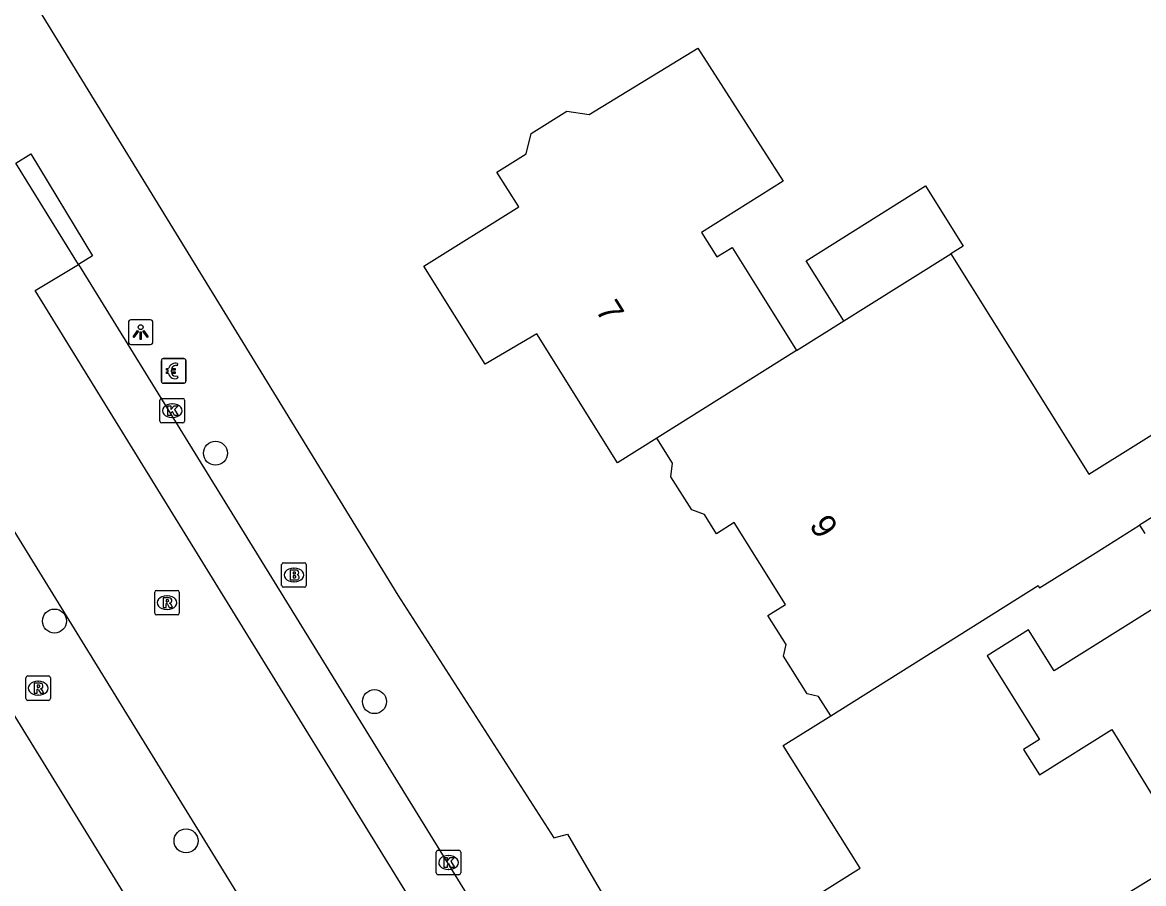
# Model space of a CAD drawing. Extents: x 161354 to 161876, y 382161 to 382804.
# Drawn here: x 161550.65 to 161596.32, y 382499.48 to 382534.56 of the extents above; entities that cross this region are included whole.
import ezdxf

# ---------------------------------------------------------------- set-up
doc = ezdxf.new("R2010")
doc.units = 0
for name, color, linetype in [('IMGEO_Betaalautomaat', 7, 'Continuous'), ('IMGEO_Boom', 7, 'Continuous'), ('IMGEO_Brandkraan', 7, 'Continuous'), ('IMGEO_Kolk', 7, 'Continuous'), ('IMGEO_Lichtpunt', 7, 'Continuous'), ('IMGEO_Pand', 7, 'Continuous'), ('IMGEO_Pand_nummerreeks', 7, 'Continuous'), ('IMGEO_Rijbaan_lokaal_gesloten', 7, 'Continuous'), ('IMGEO_Rioolput', 7, 'Continuous'), ('IMGEO_Voetpad_open', 7, 'Continuous')]:
    doc.layers.add(name, color=color, linetype=linetype)

msp = doc.modelspace()

# ---------------------------------------------------------------- linework, layer by layer
at = {"layer": 'IMGEO_Betaalautomaat'}
for p, q in [((161556.312, 382519.939), (161556.312, 382520.78)), ((161556.312, 382520.78), (161556.312, 382519.939)), ((161556.387, 382520.863), (161557.228, 382520.863)), ((161557.228, 382520.863), (161556.387, 382520.863)), ((161556.974, 382520.668), (161556.957, 382520.568)), ((161557.311, 382520.789), (161557.311, 382519.948)), ((161557.311, 382519.948), (161557.311, 382520.789)), ((161556.595, 382520.327), (161556.595, 382520.395)), ((161556.716, 382520.395), (161556.716, 382520.327)), ((161556.961, 382520.162), (161556.983, 382520.075)), ((161557.237, 382519.864), (161556.396, 382519.864)), ((161556.396, 382519.864), (161557.237, 382519.864))]:
    msp.add_line(p, q, dxfattribs=at)
for points in [[(161556.595, 382520.395), (161556.526, 382520.395), (161556.526, 382520.464), (161556.605, 382520.464)], [(161556.6, 382520.258), (161556.526, 382520.258), (161556.526, 382520.327), (161556.595, 382520.327)], [(161556.727, 382520.464), (161556.874, 382520.464), (161556.874, 382520.395), (161556.716, 382520.395)], [(161556.716, 382520.327), (161556.874, 382520.327), (161556.874, 382520.258), (161556.73, 382520.258)]]:
    msp.add_lwpolyline(points, dxfattribs=at)
for centre, radius, start, end in [((161556.39, 382520.786), 0.0779, 92.4484, 184.2845), ((161556.39, 382520.786), 0.0779, 92.4484, 184.2845), ((161556.888, 382520.388), 0.293, 73.014, 165.0139), ((161556.894, 382520.401), 0.179, 69.3236, 159.5683), ((161557.234, 382520.786), 0.0779, 2.4484, 94.2845), ((161557.234, 382520.786), 0.0779, 2.4484, 94.2845), ((161556.861, 382520.313), 0.267, 191.8096, 297.0389), ((161556.894, 382520.328), 0.179, 202.7625, 291.8693), ((161556.39, 382519.942), 0.0779, 182.4484, 274.2845), ((161556.39, 382519.942), 0.0779, 182.4484, 274.2845), ((161557.234, 382519.942), 0.0779, 272.4484, 4.2845), ((161557.234, 382519.942), 0.0779, 272.4484, 4.2845)]:
    msp.add_arc(centre, radius, start, end, dxfattribs=at)
at = {"layer": 'IMGEO_Boom'}
for centre in [(161558.515, 382517.011), (161551.957, 382510.176), (161564.991, 382506.892), (161557.316, 382501.221)]:
    msp.add_circle(centre, 0.489, dxfattribs=at)
at = {"layer": 'IMGEO_Brandkraan'}
for p, q in [((161561.212, 382511.624), (161561.212, 382512.476)), ((161561.287, 382512.55), (161562.139, 382512.55)), ((161561.7, 382512.33), (161561.725, 382512.33)), ((161562.213, 382512.476), (161562.213, 382511.624)), ((161562.139, 382511.55), (161561.287, 382511.55)), ((161561.723, 382511.77), (161561.698, 382511.77))]:
    msp.add_line(p, q, dxfattribs=at)
for points in [[(161561.212, 382511.624), (161561.212, 382512.476)], [(161561.287, 382512.55), (161562.139, 382512.55)], [(161562.213, 382512.476), (161562.213, 382511.624)], [(161561.56, 382512.25), (161561.56, 382511.85), (161561.773, 382511.85)], [(161561.791, 382512.25), (161561.56, 382512.25)], [(161561.739, 382512.169), (161561.685, 382512.169), (161561.685, 382512.093)], [(161561.685, 382512.093), (161561.738, 382512.093)], [(161561.747, 382512.017), (161561.685, 382512.017), (161561.685, 382511.936)], [(161561.685, 382511.936), (161561.747, 382511.936)], [(161562.139, 382511.55), (161561.287, 382511.55)]]:
    msp.add_lwpolyline(points, dxfattribs=at)
for centre, radius, start, end in [((161561.289, 382512.474), 0.0765, 91.552, 178.448), ((161561.289, 382512.474), 0.0765, 91.552, 178.448), ((161562.137, 382512.474), 0.0765, 1.552, 88.448), ((161562.137, 382512.474), 0.0765, 1.552, 88.448), ((161561.74, 382512.131), 0.0379, 267.8285, 90.9355), ((161561.748, 382511.976), 0.0404, 269.8759, 90.5077), ((161561.779, 382512.101), 0.251, 268.6676, 293.5347), ((161561.795, 382512.105), 0.145, 59.4692, 91.5367), ((161561.82, 382512.152), 0.0922, 285.5137, 58.1501), ((161561.825, 382511.96), 0.105, 301.3115, 78.989), ((161561.289, 382511.626), 0.0765, 181.552, 268.448), ((161561.289, 382511.626), 0.0765, 181.552, 268.448), ((161562.137, 382511.626), 0.0765, 271.552, 358.448), ((161562.137, 382511.626), 0.0765, 271.552, 358.448)]:
    msp.add_arc(centre, radius, start, end, dxfattribs=at)
for centre, major_axis, ratio, start_param, end_param in [((161561.699, 382512.05), (-0.387, 0.002), 0.722429, 4.712389, 7.853982), ((161561.724, 382512.05), (-0.39, 0.002), 0.717154, 1.570796, 4.712389)]:
    msp.add_ellipse(centre, major_axis=major_axis, ratio=ratio, start_param=start_param, end_param=end_param, dxfattribs=at)
at = {"layer": 'IMGEO_Kolk'}
for p, q in [((161556.256, 382518.319), (161556.256, 382519.171)), ((161556.331, 382519.245), (161557.183, 382519.245)), ((161557.257, 382519.171), (161557.257, 382518.319)), ((161556.744, 382519.025), (161556.769, 382519.025)), ((161556.767, 382518.465), (161556.742, 382518.465)), ((161557.183, 382518.245), (161556.331, 382518.245)), ((161567.508, 382499.913), (161567.508, 382500.765)), ((161567.583, 382500.839), (161568.435, 382500.839)), ((161567.996, 382500.619), (161568.021, 382500.619)), ((161568.509, 382500.765), (161568.509, 382499.913)), ((161568.019, 382500.059), (161567.994, 382500.059)), ((161568.435, 382499.839), (161567.583, 382499.839))]:
    msp.add_line(p, q, dxfattribs=at)
for points in [[(161556.256, 382518.319), (161556.256, 382519.171)], [(161556.331, 382519.245), (161557.183, 382519.245)], [(161557.257, 382519.171), (161557.257, 382518.319)], [(161556.577, 382518.945), (161556.7, 382518.945), (161556.7, 382518.794), (161556.83, 382518.945), (161556.994, 382518.945), (161556.848, 382518.794), (161557.001, 382518.545), (161556.849, 382518.545), (161556.764, 382518.709), (161556.7, 382518.642), (161556.7, 382518.545), (161556.577, 382518.545), (161556.577, 382518.945)], [(161557.183, 382518.245), (161556.331, 382518.245)], [(161567.508, 382499.913), (161567.508, 382500.765)], [(161567.583, 382500.839), (161568.435, 382500.839)], [(161567.829, 382500.539), (161567.952, 382500.539), (161567.952, 382500.388), (161568.082, 382500.539), (161568.246, 382500.539), (161568.1, 382500.388), (161568.253, 382500.139), (161568.101, 382500.139), (161568.016, 382500.303), (161567.952, 382500.236), (161567.952, 382500.139), (161567.829, 382500.139), (161567.829, 382500.539)], [(161568.509, 382500.765), (161568.509, 382499.913)], [(161568.435, 382499.839), (161567.583, 382499.839)]]:
    msp.add_lwpolyline(points, dxfattribs=at)
for centre, start, end in [((161556.333, 382519.169), 91.552, 178.448), ((161556.333, 382519.169), 91.552, 178.448), ((161557.181, 382519.169), 1.552, 88.448), ((161557.181, 382519.169), 1.552, 88.448), ((161556.333, 382518.321), 181.552, 268.448), ((161556.333, 382518.321), 181.552, 268.448), ((161557.181, 382518.321), 271.552, 358.448), ((161557.181, 382518.321), 271.552, 358.448), ((161567.585, 382500.763), 91.552, 178.448), ((161567.585, 382500.763), 91.552, 178.448), ((161568.433, 382500.763), 1.552, 88.448), ((161568.433, 382500.763), 1.552, 88.448), ((161567.585, 382499.915), 181.552, 268.448), ((161567.585, 382499.915), 181.552, 268.448), ((161568.433, 382499.915), 271.552, 358.448), ((161568.433, 382499.915), 271.552, 358.448)]:
    msp.add_arc(centre, 0.0765, start, end, dxfattribs=at)
for centre, major_axis, ratio, start_param, end_param in [((161556.743, 382518.745), (-0.387, 0.002), 0.722429, 4.712389, 7.853982), ((161556.768, 382518.745), (-0.39, 0.002), 0.717154, 1.570796, 4.712389), ((161567.995, 382500.339), (-0.387, 0.002), 0.722429, 4.712389, 7.853982), ((161568.02, 382500.339), (-0.39, 0.002), 0.717154, 1.570796, 4.712389)]:
    msp.add_ellipse(centre, major_axis=major_axis, ratio=ratio, start_param=start_param, end_param=end_param, dxfattribs=at)
at = {"layer": 'IMGEO_Lichtpunt'}
for p, q in [((161555.872, 382522.44), (161555.064, 382522.44)), ((161555.872, 382522.44), (161555.064, 382522.44)), ((161554.97, 382522.345), (161554.97, 382521.538)), ((161554.97, 382522.345), (161554.97, 382521.538)), ((161555.966, 382521.538), (161555.966, 382522.345)), ((161555.966, 382521.538), (161555.966, 382522.345)), ((161555.064, 382521.444), (161555.872, 382521.444)), ((161555.064, 382521.444), (161555.872, 382521.444))]:
    msp.add_line(p, q, dxfattribs=at)
for points in [[(161555.344, 382522.009), (161555.383, 382521.981), (161555.195, 382521.719), (161555.157, 382521.746), (161555.344, 382522.009)], [(161555.446, 382521.961), (161555.493, 382521.961), (161555.493, 382521.639), (161555.446, 382521.639), (161555.446, 382521.961)], [(161555.556, 382521.981), (161555.594, 382522.008), (161555.781, 382521.746), (161555.742, 382521.718), (161555.556, 382521.981)]]:
    msp.add_lwpolyline(points, dxfattribs=at)
msp.add_circle((161555.469, 382522.143), 0.0994, dxfattribs=at)
for centre, start, end in [((161555.064, 382522.345), 90, 180), ((161555.064, 382522.345), 90, 180), ((161555.872, 382522.345), 0, 90), ((161555.872, 382522.345), 0, 90), ((161555.064, 382521.538), 180, 270), ((161555.064, 382521.538), 180, 270), ((161555.872, 382521.538), 270, 0), ((161555.872, 382521.538), 270, 360)]:
    msp.add_arc(centre, 0.0946, start, end, dxfattribs=at)
at = {"layer": 'IMGEO_Pand'}
for points in [[(161576.492, 382517.623), (161574.896, 382516.624), (161571.601, 382521.877), (161569.503, 382520.632), (161567.005, 382524.624), (161570.868, 382527.041), (161569.982, 382528.457), (161571.17, 382529.2), (161571.378, 382530.038), (161572.827, 382530.945), (161573.739, 382530.807), (161578.161, 382533.51), (161581.642, 382528.093), (161578.312, 382526.008), (161578.938, 382525.008), (161579.56, 382525.397), (161580.653, 382523.65), (161582.188, 382521.197)], [(161584.105, 382522.4), (161582.572, 382524.85), (161587.439, 382527.896), (161588.969, 382525.451), (161588.472, 382525.139)], [(161584.105, 382522.4), (161585.018, 382522.972), (161588.472, 382525.139)], [(161588.472, 382525.139), (161594.096, 382516.151), (161598.136, 382518.679), (161599.647, 382516.264), (161596.153, 382514.078)], [(161582.188, 382521.197), (161584.105, 382522.4)], [(161582.188, 382521.197), (161576.492, 382517.623)], [(161583.577, 382506.313), (161583.079, 382507.108), (161582.617, 382507.212), (161581.659, 382508.742), (161581.756, 382509.222), (161581.014, 382510.407), (161581.729, 382510.855), (161579.647, 382514.183), (161578.927, 382513.733), (161578.434, 382514.521), (161577.914, 382514.706), (161577.07, 382516.055), (161577.131, 382516.602), (161576.492, 382517.623)], [(161583.577, 382506.313), (161592.03, 382511.624), (161592.087, 382511.533), (161594.233, 382512.876), (161594.602, 382513.107), (161596.153, 382514.078)], [(161596.153, 382514.078), (161596.366, 382513.738)], [(161597.841, 382511.381), (161592.677, 382508.149), (161591.636, 382509.813), (161589.948, 382508.757), (161592.079, 382505.352), (161591.429, 382504.945), (161592.079, 382503.906), (161595.029, 382505.751), (161595.565, 382504.879), (161598.182, 382500.619)], [(161597.174, 382500), (161593.876, 382497.975), (161593.651, 382497.019), (161592.397, 382496.245), (161591.465, 382496.465), (161590.363, 382495.784), (161589.486, 382497.203), (161585.66, 382494.839), (161583.063, 382499.041), (161584.604, 382500), (161584.77, 382500.103), (161581.642, 382505.102), (161583.577, 382506.313)]]:
    msp.add_lwpolyline(points, dxfattribs=at)
at = {"layer": 'IMGEO_Rijbaan_lokaal_gesloten'}
for points in [[(161577.112, 382470.322), (161575.449, 382473.073), (161561.101, 382496.334), (161558.843, 382500), (161550.097, 382514.2), (161540.821, 382529.326)], [(161552.932, 382524.704), (161550.387, 382528.832)], [(161576.74, 382486.091), (161575.005, 382484.986), (161551.177, 382523.64), (161552.932, 382524.704)]]:
    msp.add_lwpolyline(points, dxfattribs=at)
at = {"layer": 'IMGEO_Rioolput'}
for p, q in [((161556.117, 382511.424), (161556.969, 382511.424)), ((161556.042, 382510.498), (161556.042, 382511.35)), ((161556.53, 382511.204), (161556.555, 382511.204)), ((161557.043, 382511.35), (161557.043, 382510.498)), ((161556.553, 382510.644), (161556.528, 382510.644)), ((161556.969, 382510.424), (161556.117, 382510.424)), ((161550.793, 382507.014), (161550.793, 382507.866)), ((161550.868, 382507.94), (161551.72, 382507.94)), ((161551.794, 382507.866), (161551.794, 382507.014)), ((161551.281, 382507.72), (161551.306, 382507.72)), ((161551.72, 382506.94), (161550.868, 382506.94)), ((161551.304, 382507.16), (161551.279, 382507.16))]:
    msp.add_line(p, q, dxfattribs=at)
for points in [[(161556.117, 382511.424), (161556.969, 382511.424)], [(161556.042, 382510.498), (161556.042, 382511.35)], [(161556.631, 382511.122), (161556.379, 382511.124), (161556.379, 382510.724)], [(161556.557, 382511.043), (161556.503, 382511.043), (161556.503, 382510.962)], [(161556.503, 382510.962), (161556.555, 382510.962)], [(161557.043, 382511.35), (161557.043, 382510.498)], [(161556.379, 382510.724), (161556.503, 382510.724), (161556.503, 382510.886), (161556.514, 382510.886)], [(161556.561, 382510.857), (161556.632, 382510.724), (161556.772, 382510.724), (161556.707, 382510.85)], [(161556.969, 382510.424), (161556.117, 382510.424)], [(161550.793, 382507.014), (161550.793, 382507.866)], [(161550.868, 382507.94), (161551.72, 382507.94)], [(161551.794, 382507.866), (161551.794, 382507.014)], [(161551.382, 382507.638), (161551.13, 382507.64), (161551.13, 382507.24)], [(161551.13, 382507.24), (161551.254, 382507.24), (161551.254, 382507.402), (161551.265, 382507.402)], [(161551.308, 382507.559), (161551.254, 382507.559), (161551.254, 382507.478)], [(161551.254, 382507.478), (161551.306, 382507.478)], [(161551.312, 382507.373), (161551.383, 382507.24), (161551.523, 382507.24), (161551.458, 382507.366)], [(161551.72, 382506.94), (161550.868, 382506.94)]]:
    msp.add_lwpolyline(points, dxfattribs=at)
for centre, radius, start, end in [((161556.119, 382511.348), 0.0765, 91.552, 178.448), ((161556.119, 382511.348), 0.0765, 91.552, 178.448), ((161556.967, 382511.348), 0.0765, 1.552, 88.448), ((161556.967, 382511.348), 0.0765, 1.552, 88.448), ((161556.539, 382511.151), 0.19, 274.7715, 282.9687), ((161556.563, 382510.947), 0.0964, 77.0061, 93.1865), ((161556.577, 382511.004), 0.0378, 276.6634, 79.6772), ((161556.63, 382511.012), 0.109, 350.3612, 89.416), ((161556.628, 382511.012), 0.112, 277.5842, 350.9817), ((161556.119, 382510.5), 0.0765, 181.552, 268.448), ((161556.119, 382510.5), 0.0765, 181.552, 268.448), ((161556.513, 382510.833), 0.0533, 26.0293, 88.6989), ((161556.612, 382510.797), 0.108, 29.5134, 73.7905), ((161556.967, 382510.5), 0.0765, 271.552, 358.448), ((161556.967, 382510.5), 0.0765, 271.552, 358.448), ((161550.87, 382507.864), 0.0765, 91.552, 178.448), ((161550.87, 382507.864), 0.0765, 91.552, 178.448), ((161551.718, 382507.864), 0.0765, 1.552, 88.448), ((161551.718, 382507.864), 0.0765, 1.552, 88.448), ((161551.264, 382507.349), 0.0533, 26.0293, 88.6989), ((161551.29, 382507.667), 0.19, 274.7715, 282.9687), ((161551.314, 382507.463), 0.0964, 77.0061, 93.1865), ((161551.328, 382507.52), 0.0378, 276.6634, 79.6772), ((161551.381, 382507.528), 0.109, 350.3612, 89.416), ((161551.379, 382507.528), 0.112, 277.5842, 350.9817), ((161551.363, 382507.313), 0.108, 29.5134, 73.7905), ((161550.87, 382507.016), 0.0765, 181.552, 268.448), ((161550.87, 382507.016), 0.0765, 181.552, 268.448), ((161551.718, 382507.016), 0.0765, 271.552, 358.448), ((161551.718, 382507.016), 0.0765, 271.552, 358.448)]:
    msp.add_arc(centre, radius, start, end, dxfattribs=at)
for centre, major_axis, ratio, start_param, end_param in [((161556.529, 382510.924), (-0.387, 0.002), 0.722429, 4.712389, 7.853982), ((161556.554, 382510.924), (-0.39, 0.002), 0.717154, 1.570796, 4.712389), ((161551.28, 382507.44), (-0.387, 0.002), 0.722429, 4.712389, 7.853982), ((161551.305, 382507.44), (-0.39, 0.002), 0.717154, 1.570796, 4.712389)]:
    msp.add_ellipse(centre, major_axis=major_axis, ratio=ratio, start_param=start_param, end_param=end_param, dxfattribs=at)
at = {"layer": 'IMGEO_Voetpad_open'}
for points in [[(161537.341, 382557.85), (161565.95, 382511.235), (161572.292, 382501.343), (161572.851, 382501.493), (161573.727, 382500), (161581.489, 382486.772), (161593.113, 382483.942)], [(161550.387, 382528.832), (161550.995, 382529.201), (161553.512, 382525.056), (161552.932, 382524.704)], [(161537.314, 382527.427), (161542.448, 382519.098), (161554.214, 382500), (161556.561, 382496.19), (161570.48, 382473.695), (161567.506, 382461.215)], [(161552.932, 382524.704), (161576.74, 382486.091)]]:
    msp.add_lwpolyline(points, dxfattribs=at)

# ---------------------------------------------------------------- texts
at = {"layer": 'IMGEO_Pand_nummerreeks'}
for s, rotation, p in [('7', 302.0969, (161573.971, 382522.842)), ('9', 302.0281, (161582.679, 382514.088))]:
    msp.add_text(s, height=1, rotation=rotation, dxfattribs=at).set_placement(p)

doc.saveas('drawing.dxf')
